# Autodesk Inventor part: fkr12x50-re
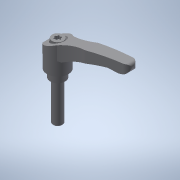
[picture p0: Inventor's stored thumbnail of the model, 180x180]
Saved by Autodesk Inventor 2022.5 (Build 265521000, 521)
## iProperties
Created: 2017-09
Part Number: fkr12x50-re
Material: 一般
Document SubType Name: Modeling
Designer: imaocorp
Density: 1 g/cm^3
Appearance: 既定
Author: imaocorp
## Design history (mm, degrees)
node "fkr12x50-re.x_t1"
node "fkr12x50-re"
node "Base1"
